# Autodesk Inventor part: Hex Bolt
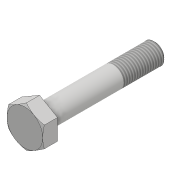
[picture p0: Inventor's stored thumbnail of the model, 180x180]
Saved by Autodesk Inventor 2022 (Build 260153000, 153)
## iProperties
Created: 2016-05
Part Number: Hex Bolt
Material: Generic
Document SubType Name: Modeling
Designer: CADCIM
Density: 1 g/cm^3
Appearance: Default
Author: CADCIM
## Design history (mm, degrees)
sketch "Sketch1"
  geometry: L1 (0, -19.63)-(-17, -9.815); L2 (-17, -9.815)-(-17, 9.815); L3 (-17, 9.815)-(0, 19.63); L4 (0, 19.63)-(17, 9.815); L5 (17, 9.815)-(17, -9.815); L6 (17, -9.815)-(0, -19.63); 2 further points
  constraints: 12 end point, 1 coincident, 13 other
  dimensions: "d0" = 34 distance between parallel lines of L2 L5
extrude "Extrusion1" new body sketch "Sketch1" distance "d1" = 14; taper "d2" = 0 deg
sketch "Sketch2"
  geometry: 1 further point
sketch "Sketch3"
  geometry: C1 r 10 at (0, 0); 1 further point
  constraints: 1 centre point, 1 coincident
  dimensions: "d3" = 20 diameter of C1
extrude "Extrusion2" join sketch "Sketch3" distance "d4" = 110; taper "d5" = 0 deg
thread "Thread1" dims "d6" = 40, "d7" = 0
sketch "Sketch4"
  geometry: L1 (0, -19.63)-(17, -9.815) reference; C1 r 17 at (0, 0); 1 further point
  constraints: 1 centre point, 1 coincident, 1 tangent
extrude "Extrusion3" sketch "Sketch4" distance "d8" = 200; taper "d9" = 60 deg
chamfer "Chamfer1" distance "d10" = 1.5; stored, may be unused: second distance "d11" = 2, angle "d12" = 45 deg
body "Solid1"
